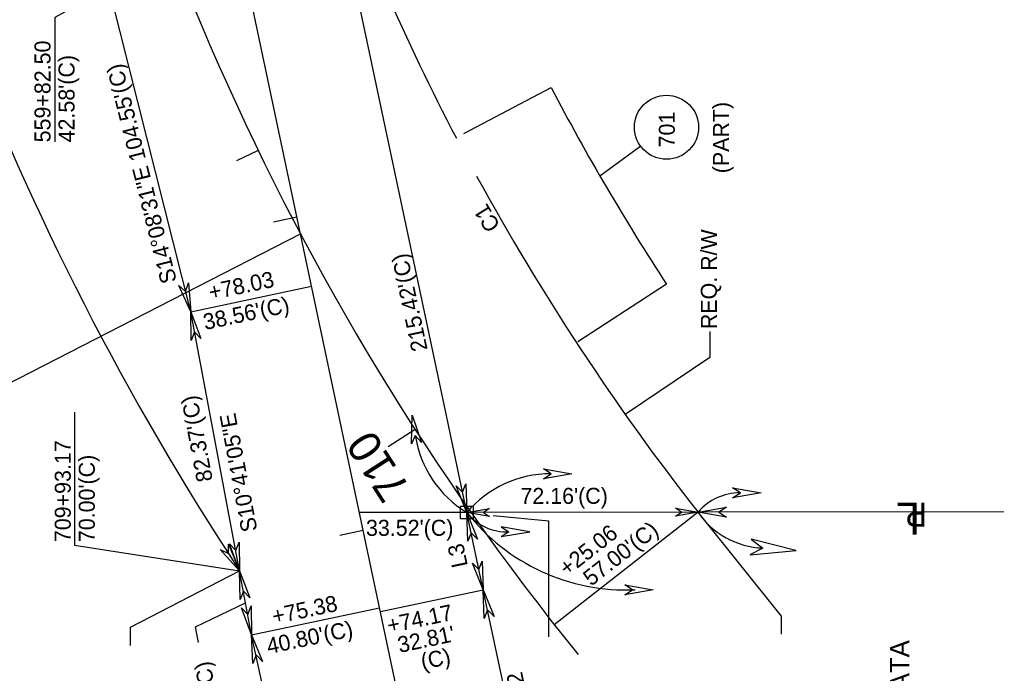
# Model space of a CAD drawing. Extents: x 2003883 to 2008298, y 399149 to 424047.
# Drawn here: x 2005903 to 2006208, y 403140 to 403344.2 of the extents above; entities that cross this region are included whole.
import ezdxf

# ---------------------------------------------------------------- set-up
doc = ezdxf.new("R2010")
doc.units = 0
for name, color, linetype in [('BaselineSurvey', 7, 'Continuous'), ('BaselineTextWt1', 7, 'Continuous'), ('BaselineTextWt2', 7, 'Continuous'), ('EaseTempLine', 7, 'Continuous'), ('MonConcOpen', 7, 'Continuous'), ('MonText', 7, 'Continuous'), ('ParcelBubble700', 7, 'Continuous'), ('PropertyLine_ep', 7, 'Continuous'), ('PropertyLineStaTie_ep', 7, 'Continuous'), ('PropertyLineSymbol_ep', 7, 'Continuous'), ('PropertyLineText_ep', 7, 'Continuous'), ('RWandLA_StaTie', 7, 'Continuous'), ('RWandLA_StaTie_ep', 7, 'Continuous'), ('RWandLA_Text', 7, 'Continuous'), ('RWandLA_Text_ep', 7, 'Continuous'), ('RWLine', 7, 'Continuous'), ('RWLine_ep', 7, 'Continuous')]:
    doc.layers.add(name, color=color, linetype=linetype)

msp = doc.modelspace()

# ---------------------------------------------------------------- linework, layer by layer
at = {"layer": 'BaselineSurvey'}
for p, q in [((2006223.38, 402176.93), (2005921.59, 403604.26)), ((2005977.52, 403303.31), (2005970.77, 403300.04)), ((2005989.63, 403282.43), (2005982.3, 403280.88)), ((2006026.5, 403216.19), (2006018.09, 403210.77)), ((2006010.32, 403184.59), (2006002.98, 403183.04))]:
    msp.add_line(p, q, dxfattribs=at)
msp.add_arc((2006714.61, 403660.33), 819, 188.65379, 218.91586, dxfattribs=at)
at = {"layer": 'BaselineTextWt1'}
msp.add_lwpolyline([(2005886.59, 403154.95), (2005886.59, 403223.83), (2005990.73, 403277.23)], dxfattribs=at)
at = {"layer": 'EaseTempLine'}
for p, q in [((2006041.67, 403308.65), (2006068.99, 403322.93)), ((2006104.98, 403261.57), (2006077.35, 403243.5))]:
    msp.add_line(p, q, dxfattribs=at)
msp.add_arc((2006714.63, 403660.37), 728.5, 207.59325, 213.18991, dxfattribs=at)
at = {"layer": 'MonConcOpen'}
msp.add_lwpolyline([(2006040.66, 403188.23), (2006040.66, 403192.23), (2006044.66, 403192.23), (2006044.66, 403188.23)], close=True, dxfattribs=at)
at = {"layer": 'MonText'}
msp.add_lwpolyline([(2006068.28, 403151.37), (2006068.28, 403187.51), (2006050.9, 403189.21)], dxfattribs=at)
at = {"layer": 'ParcelBubble700'}
msp.add_line((2006096.92, 403304.65), (2006084.19, 403295.32), dxfattribs=at)
msp.add_circle((2006104.98, 403310.56), 10, dxfattribs=at)
at = {"layer": 'PropertyLine_ep'}
msp.add_line((2006114.83, 403190.33), (2006042.66, 403190.23), dxfattribs=at)
at = {"layer": 'PropertyLineStaTie_ep'}
msp.add_line((2006042.66, 403190.23), (2006009.14, 403190.19), dxfattribs=at)
at = {"layer": 'PropertyLineText_ep'}
for p, q in [((2006025.41, 403211.65), (2006025.54, 403220.63)), ((2006025.54, 403220.63), (2006028.47, 403212.14)), ((2006026.56, 403214.27), (2006025.41, 403211.65)), ((2006028.47, 403212.14), (2006026.56, 403214.27)), ((2006066.55, 403203.87), (2006075.4, 403202.32)), ((2006068.95, 403202.32), (2006066.55, 403203.87)), ((2006075.4, 403202.32), (2006066.55, 403200.77)), ((2006066.55, 403200.77), (2006068.95, 403202.32)), ((2006125.63, 403197.93), (2006134.48, 403196.38)), ((2006128.03, 403196.38), (2006125.63, 403197.93)), ((2006134.48, 403196.38), (2006125.63, 403194.83)), ((2006125.63, 403194.83), (2006128.03, 403196.38)), ((2006062.26, 403184.18), (2006053.36, 403185.73)), ((2006053.36, 403185.73), (2006055.76, 403184.18)), ((2006055.76, 403184.18), (2006053.36, 403182.68)), ((2006053.39, 403182.7), (2006062.29, 403184.2))]:
    msp.add_line(p, q, dxfattribs=at)
for centre, radius, start, end in [((2006060.28, 403219.44), 34.11, 188.7916, 238.9005), ((2006068.7, 403168.2), 34.11, 89.6546, 139.7635), ((2006127.85, 403179.31), 17.06, 89.6546, 139.7635), ((2006055.13, 403200.04), 15.86, 218.1943, 272.3877)]:
    msp.add_arc(centre, radius, start, end, dxfattribs=at)
at = {"layer": 'RWandLA_StaTie'}
msp.add_line((2006114.83, 403190.33), (2006069.96, 403155.17), dxfattribs=at)
at = {"layer": 'RWandLA_StaTie_ep'}
for p, q in [((2005956.46, 403252.96), (2005994.18, 403260.94)), ((2006015.67, 403159.32), (2006047.76, 403166.1)), ((2005975.49, 403152.06), (2006015.42, 403160.5))]:
    msp.add_line(p, q, dxfattribs=at)
at = {"layer": 'RWandLA_Text'}
for p, q in [((2006114.83, 403190.33), (2006123.67, 403191.89)), ((2006123.67, 403191.89), (2006121.28, 403190.34)), ((2006123.68, 403188.79), (2006114.83, 403190.33)), ((2006121.28, 403190.34), (2006123.68, 403188.79)), ((2006145.39, 403178.37), (2006131.37, 403181.89)), ((2006131.37, 403181.89), (2006135.02, 403179.13)), ((2005971.73, 403172.02), (2005965.65, 403178.64)), ((2005965.65, 403178.64), (2005968.25, 403177.45)), ((2005968.25, 403177.45), (2005968.26, 403180.31)), ((2005968.26, 403180.31), (2005971.73, 403172.02)), ((2006135.02, 403179.13), (2006131.01, 403177.02)), ((2006131.05, 403177.04), (2006145.43, 403178.38)), ((2006091.95, 403167.61), (2006100.8, 403166.06)), ((2006094.35, 403166.06), (2006091.95, 403167.61)), ((2006100.8, 403166.06), (2006091.95, 403164.51)), ((2006091.95, 403164.51), (2006094.35, 403166.06))]:
    msp.add_line(p, q, dxfattribs=at)
for points in [[(2006118.47, 403246.79), (2006118.47, 403238.66), (2006092.1, 403220.87)], [(2005920.21, 403221.56), (2005920.21, 403180.01), (2005971.73, 403172.02)], [(2006140.91, 403152.2), (2006140.91, 403157.9), (2006114.83, 403190.33)], [(2005937.66, 403148.69), (2005937.66, 403154.38), (2005971.73, 403172.02)]]:
    msp.add_lwpolyline(points, dxfattribs=at)
for centre, radius, start, end in [((2006092.51, 403229.46), 63.43, 218.1943, 272.3877), ((2006135.87, 403204.51), 25.37, 213.9732, 268.1666)]:
    msp.add_arc(centre, radius, start, end, dxfattribs=at)
at = {"layer": 'RWandLA_Text_ep'}
for p, q in [((2005956.46, 403252.96), (2005952.79, 403261.16)), ((2005952.79, 403261.16), (2005954.88, 403259.21)), ((2005954.88, 403259.21), (2005955.8, 403261.92)), ((2005955.8, 403261.92), (2005956.46, 403252.96)), ((2005956.57, 403243.98), (2005956.46, 403252.96)), ((2005956.46, 403252.96), (2005959.62, 403244.55)), ((2005957.65, 403246.62), (2005956.57, 403243.98)), ((2005959.62, 403244.55), (2005957.65, 403246.62)), ((2006042.66, 403190.23), (2006039.32, 403198.57)), ((2006039.32, 403198.57), (2006041.33, 403196.54)), ((2006041.33, 403196.54), (2006042.35, 403199.21)), ((2006042.35, 403199.21), (2006042.66, 403190.23)), ((2006042.66, 403190.23), (2006049.74, 403191.48)), ((2006049.74, 403191.48), (2006047.82, 403190.24)), ((2006109.67, 403190.32), (2006107.74, 403191.56)), ((2006107.74, 403191.56), (2006114.83, 403190.33)), ((2006049.74, 403189), (2006042.66, 403190.23)), ((2006042.98, 403181.25), (2006042.66, 403190.23)), ((2006042.66, 403190.23), (2006046.01, 403181.9)), ((2006047.82, 403190.24), (2006049.74, 403189)), ((2006114.83, 403190.33), (2006107.75, 403189.08)), ((2006107.75, 403189.08), (2006109.67, 403190.32)), ((2006044, 403183.92), (2006042.98, 403181.25)), ((2006046.01, 403181.9), (2006044, 403183.92)), ((2005971.73, 403172.02), (2005968.56, 403180.43)), ((2005968.56, 403180.43), (2005970.53, 403178.36)), ((2005970.53, 403178.36), (2005971.61, 403181)), ((2005971.61, 403181), (2005971.73, 403172.02)), ((2006047.76, 403166.1), (2006044.42, 403174.44)), ((2006044.42, 403174.44), (2006046.43, 403172.41)), ((2006046.43, 403172.41), (2006047.45, 403175.08)), ((2006047.45, 403175.08), (2006047.76, 403166.1)), ((2005971.85, 403163.04), (2005971.73, 403172.02)), ((2005971.73, 403172.02), (2005974.89, 403163.61)), ((2005972.92, 403165.68), (2005971.85, 403163.04)), ((2005974.89, 403163.61), (2005972.92, 403165.68)), ((2006048.1, 403157.13), (2006047.76, 403166.1)), ((2006047.76, 403166.1), (2006051.14, 403157.78)), ((2005975.49, 403152.06), (2005972.33, 403160.47)), ((2005972.33, 403160.47), (2005974.3, 403158.4)), ((2005974.3, 403158.4), (2005975.38, 403161.04)), ((2005975.38, 403161.04), (2005975.49, 403152.06)), ((2006049.12, 403159.8), (2006048.1, 403157.13)), ((2006051.14, 403157.78), (2006049.12, 403159.8)), ((2005975.84, 403143.08), (2005975.49, 403152.06)), ((2005975.49, 403152.06), (2005978.87, 403143.73)), ((2005976.85, 403145.76), (2005975.84, 403143.08)), ((2005978.87, 403143.73), (2005976.85, 403145.76))]:
    msp.add_line(p, q, dxfattribs=at)
for points in [[(2005914.14, 403306), (2005914.14, 403344.92), (2005930.91, 403354.34)], [(2005958.86, 403149.66), (2005957.95, 403154.51), (2005973.61, 403162.04)]]:
    msp.add_lwpolyline(points, dxfattribs=at)
at = {"layer": 'RWLine'}
msp.add_line((2006617.07, 403190.99), (2006114.83, 403190.33), dxfattribs=at)
for radius, start, end in [(889, 188.4719, 213.31785), (762, 199.89785, 207.61239), (762, 208.61998, 218.083)]:
    msp.add_arc((2006714.61, 403660.33), radius, start, end, dxfattribs=at)
at = {"layer": 'RWLine_ep'}
for p, q in [((2006035.95, 403222), (2005998.1, 403400.99)), ((2005956.46, 403252.96), (2005930.91, 403354.34)), ((2005971.73, 403172.02), (2005956.46, 403252.96)), ((2006042.66, 403190.23), (2006035.95, 403222)), ((2006047.76, 403166.1), (2006042.66, 403190.23)), ((2005975.49, 403152.06), (2005971.73, 403172.02)), ((2006061.52, 403101.95), (2006047.76, 403166.1)), ((2005995.72, 403058), (2005975.49, 403152.06))]:
    msp.add_line(p, q, dxfattribs=at)

# ---------------------------------------------------------------- texts
at = {"layer": 'BaselineTextWt1'}
msp.add_text('¡ CONST. CURVE DATA', height=6, rotation=90, dxfattribs=at).set_placement((2006180.73, 403061.19))
at = {"layer": 'BaselineTextWt2'}
msp.add_text('710', height=10, rotation=122.8401, dxfattribs=at).set_placement((2006025.12, 403197.89))
at = {"layer": 'ParcelBubble700'}
for s, p in [('(PART)', (2006124.49, 403296.19)), ('701', (2006107.58, 403304.26))]:
    msp.add_text(s, height=5, rotation=90, dxfattribs=at).set_placement(p)
at = {"layer": 'PropertyLineSymbol_ep'}
for s, height, p in [('L', 10, (2006184.17, 403193.35)), ('P', 7.5, (2006186.27, 403193.3))]:
    msp.add_text(s, height=height, rotation=180.0801, dxfattribs=at).set_placement(p)
at = {"layer": 'PropertyLineText_ep'}
for s, p in [("72.16'(C)", (2006059.39, 403192.91)), ("33.52'(C)", (2006011.18, 403182.93))]:
    msp.add_text(s, height=5, rotation=0.0758, dxfattribs=at).set_placement(p)
at = {"layer": 'RWandLA_Text'}
for s, rotation, p in [('C1', 121.883, (2006053.28, 403279.83)), ('REQ. R/W', 90, (2006120.7, 403247.5)), ('709+93.17', 90, (2005919.02, 403180.98)), ("70.00'(C)", 90, (2005926.52, 403180.98)), ('+25.06', 38.083, (2006073.95, 403170.18)), ("57.00'(C)", 38.083, (2006081.46, 403167.04))]:
    msp.add_text(s, height=5, rotation=rotation, dxfattribs=at).set_placement(p)
at = {"layer": 'RWandLA_Text_ep'}
for s, rotation, p in [('559+82.50', 90, (2005912.7, 403305.84)), ("42.58'(C)", 90, (2005920.2, 403305.84)), ('S14°08\'31"E 104.55\'(C)', 104.142, (2005952.16, 403262.47)), ("215.42'(C)", 101.9389, (2006030.43, 403241.14)), ('+78.03', 11.9389, (2005962.66, 403256.51)), ("38.56'(C)", 11.9389, (2005960.94, 403247.21)), ("82.37'(C)", 100.6847, (2005963.38, 403200.3)), ('S10°41\'05"E', 100.6847, (2005977.31, 403184.68)), ('L3', 101.9389, (2006042.99, 403173.61)), ('+75.38', 11.9389, (2005982.45, 403155.28)), ('+74.17', 11.9389, (2006018.37, 403152.45)), ("40.80'(C)", 11.9389, (2005980.77, 403145.98)), ("32.81'", 11.9389, (2006021.65, 403146.36)), ('(C)', 11.9389, (2006028.87, 403141.11)), ("20.31'(C)", 100.6847, (2005967.52, 403117.23)), ('L2', 102.105, (2006061.39, 403133.48))]:
    msp.add_text(s, height=5, rotation=rotation, dxfattribs=at).set_placement(p)

doc.saveas('drawing.dxf')
